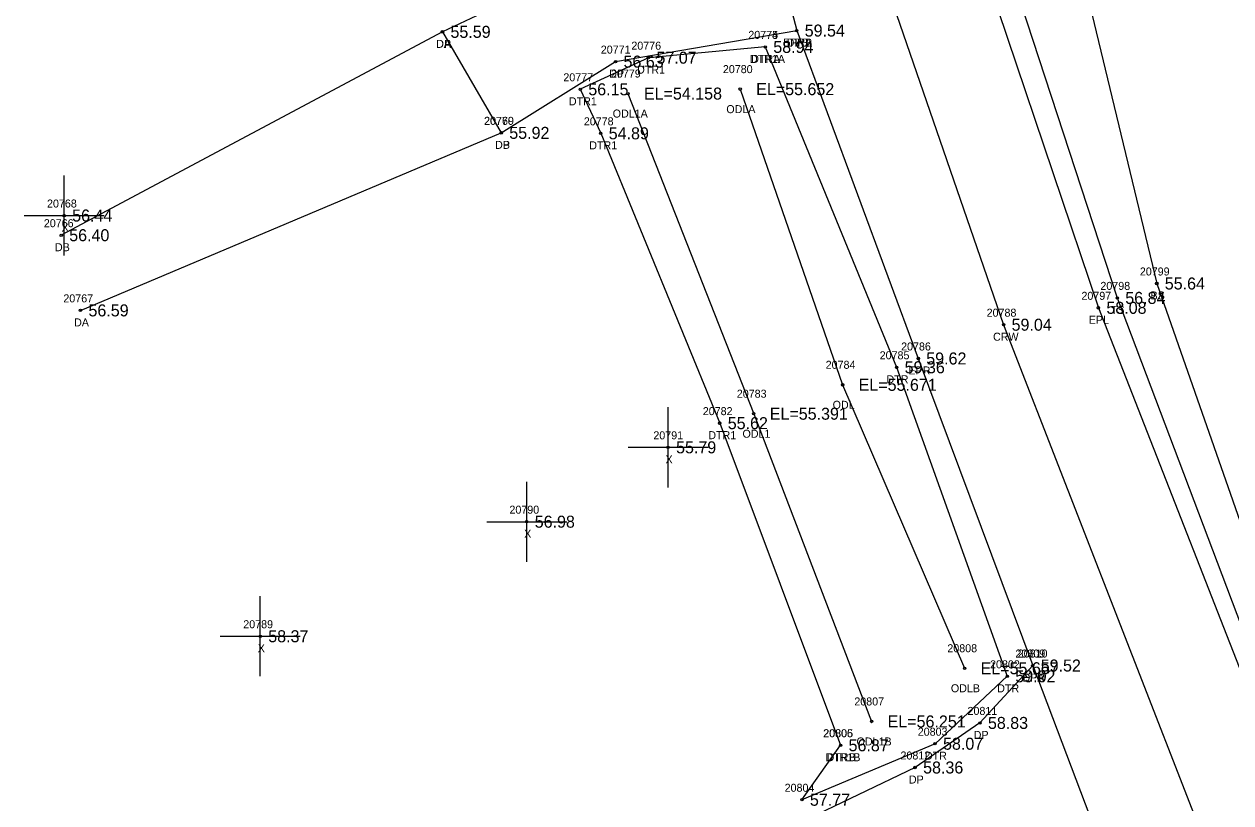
# Model space of a CAD drawing. Extents: x 2396547 to 2397655, y 770185 to 772649.
# Drawn here: x 2396996.6 to 2397147.4, y 771116.1 to 771213.4 of the extents above; entities that cross this region are included whole.
import ezdxf

# ---------------------------------------------------------------- set-up
doc = ezdxf.new("R2010")
doc.units = 0
for name, color, linetype in [('RD_DTM_BkLn1', 7, 'Continuous'), ('RD_DTM_BkLn2', 7, 'Continuous'), ('RD_DTM_BkLn_txCode', 7, 'Continuous'), ('RD_EX_Driveway', 7, 'Continuous'), ('RD_EX_Driveway_txCode', 7, 'Continuous'), ('RD_EX_H2O', 7, 'Continuous'), ('RD_EX_H2O_txCode', 7, 'Continuous'), ('RD_EX_Misc', 7, 'Continuous'), ('RD_EX_Misc_txCode', 7, 'Continuous'), ('RD_EX_Road', 7, 'Continuous'), ('RD_EX_Road_txCode', 7, 'Continuous'), ('RD_EX_TX_Driveway_ELEV', 7, 'Continuous'), ('RD_EX_TX_H2O_ELEV', 7, 'Continuous'), ('RD_EX_TX_Misc_ELEV', 7, 'Continuous'), ('RD_EX_TX_Road_ELEV', 7, 'Continuous'), ('RD_HC_Survey_ELEV', 7, 'Continuous'), ('RD_HC_Survey_txCode', 7, 'Continuous'), ('RD_SMD_Locator', 7, 'Continuous')]:
    doc.layers.add(name, color=color, linetype=linetype)

msp = doc.modelspace()

# ---------------------------------------------------------------- linework, layer by layer
at = {"layer": 'RD_DTM_BkLn1'}
msp.add_lwpolyline([(2397104.78, 771217.07), (2397119.02, 771175.87), (2397143.13, 771113.88), (2397170.45, 771052.64), (2397197.01, 770999.9), (2397235.12, 770930.63), (2397270.14, 770871.5)], dxfattribs=at)
at = {"layer": 'RD_DTM_BkLn2'}
for points in [[(2397076.78, 771367.04), (2397097.18, 771355.59), (2397095.19, 771340.51), (2397107.46, 771294.95), (2397125.86, 771232.19), (2397125.86, 771232.19), (2397138.17, 771181.02), (2397159.24, 771120.76), (2397175.38, 771088.12), (2397179.45, 771097.49), (2397196.45, 771092.84), (2397253.33, 771096.54)], [(2397076.87, 771363.73), (2397092.63, 771353.52), (2397090.96, 771344.27), (2397084.99, 771338.48), (2397096.6, 771290.87), (2397116.69, 771229.78), (2397116.69, 771229.78), (2397133.23, 771179.22), (2397155.87, 771119.34), (2397173.3, 771081.82), (2397181.13, 771084.07), (2397253.33, 771087)]]:
    msp.add_lwpolyline(points, dxfattribs=at)
at = {"layer": 'RD_EX_Driveway'}
for p, q in [((2397048.88, 771212.46), (2397001.22, 771187.05)), ((2397003.63, 771177.66), (2397056.23, 771199.84))]:
    msp.add_line(p, q, dxfattribs=at)
for points in [[(2397086.26, 771238.89), (2397083.76, 771232.99), (2397079.93, 771229.79), (2397073.08, 771224.62), (2397063.07, 771219.15), (2397048.88, 771212.46), (2397056.23, 771199.84), (2397070.51, 771208.74), (2397093.16, 771212.62)], [(2397122.66, 771133.29), (2397116.06, 771126.12), (2397107.96, 771120.55), (2397093.7, 771113.7), (2397099.75, 771102.64), (2397113.7, 771107.54), (2397125.39, 771110.49), (2397131.66, 771109.5)]]:
    msp.add_lwpolyline(points, dxfattribs=at)
at = {"layer": 'RD_EX_H2O'}
for points in [[(2397089.23, 771210.58), (2397074.63, 771209.23), (2397066.11, 771205.28), (2397068.66, 771199.78), (2397083.54, 771163.57), (2397098.64, 771123.33)], [(2397089.23, 771210.58), (2397105.65, 771170.55), (2397119.48, 771131.94), (2397110.45, 771123.52), (2397093.81, 771116.52), (2397098.64, 771123.33)], [(2397072.06, 771204.75), (2397087.79, 771164.75), (2397102.52, 771126.3)], [(2397086.09, 771205.3), (2397098.9, 771168.36), (2397114.14, 771132.95)]]:
    msp.add_lwpolyline(points, dxfattribs=at)
at = {"layer": 'RD_EX_Misc'}
for p, q in [((2397001.59, 771184.51), (2397001.59, 771194.51)), ((2396996.59, 771189.51), (2397006.59, 771189.51)), ((2397077.08, 771155.55), (2397077.08, 771165.55)), ((2397072.08, 771160.55), (2397082.08, 771160.55)), ((2397059.41, 771146.26), (2397059.41, 771156.26)), ((2397054.41, 771151.26), (2397064.41, 771151.26)), ((2397026.1, 771131.95), (2397026.1, 771141.95)), ((2397021.1, 771136.95), (2397031.1, 771136.95))]:
    msp.add_line(p, q, dxfattribs=at)
at = {"layer": 'RD_EX_Road'}
for points in [[(2397051, 771358.07), (2397072.97, 771279.15), (2397086.26, 771238.89), (2397093.16, 771212.62)], [(2397113.76, 771228.75), (2397130.87, 771177.98), (2397154.19, 771118.49), (2397170.38, 771081.25), (2397178.53, 771063.49), (2397207.96, 771004.56), (2397238.54, 770949.11), (2397245.72, 770936.59), (2397280.76, 770876.73)], [(2397093.16, 771212.62), (2397108.35, 771171.65), (2397122.66, 771133.29), (2397131.66, 771109.5), (2397159.86, 771046.96), (2397187.02, 770992.86), (2397227.29, 770920.43), (2397260.16, 770864.73)]]:
    msp.add_lwpolyline(points, dxfattribs=at)
at = {"layer": 'RD_SMD_Locator'}
for centre in [(2397048.88, 771212.46), (2397048.88, 771212.46), (2397093.16, 771212.62), (2397093.16, 771212.62), (2397093.16, 771212.62), (2397089.23, 771210.58), (2397089.23, 771210.58), (2397074.63, 771209.23), (2397070.51, 771208.74), (2397066.11, 771205.28), (2397072.06, 771204.75), (2397086.09, 771205.3), (2397056.23, 771199.84), (2397056.23, 771199.84), (2397068.66, 771199.78), (2397001.59, 771189.51), (2397001.22, 771187.05), (2397138.17, 771181.02), (2397133.23, 771179.22), (2397003.63, 771177.66), (2397130.87, 771177.98), (2397119.02, 771175.87), (2397108.35, 771171.65), (2397105.65, 771170.55), (2397098.9, 771168.36), (2397087.79, 771164.75), (2397083.54, 771163.57), (2397077.08, 771160.55), (2397059.41, 771151.26), (2397026.1, 771136.95), (2397114.14, 771132.95), (2397122.66, 771133.29), (2397122.66, 771133.29), (2397119.48, 771131.94), (2397102.52, 771126.3), (2397116.06, 771126.12), (2397098.64, 771123.33), (2397098.64, 771123.33), (2397110.45, 771123.52), (2397107.96, 771120.55), (2397093.81, 771116.52)]:
    msp.add_circle(centre, 0.15, dxfattribs=at)

# ---------------------------------------------------------------- texts
at = {"layer": 'RD_DTM_BkLn_txCode'}
for s, p in [('20799', (2397136.05, 771182.02)), ('20798', (2397131.12, 771180.22)), ('BS', (2397137.39, 771179.02)), ('TS', (2397132.44, 771177.22))]:
    msp.add_text(s, height=1, dxfattribs=at).set_placement(p)
at = {"layer": 'RD_EX_Driveway_txCode'}
for s, p in [('DA', (2397048.08, 771210.46)), ('DP', (2397048.1, 771210.46)), ('20771', (2397068.67, 771209.74)), ('DPB', (2397091.9, 771210.62)), ('DP', (2397069.73, 771206.74)), ('20770', (2397054.07, 771200.84)), ('20769', (2397054.09, 771200.84)), ('DB', (2397055.45, 771197.84)), ('DP', (2397055.45, 771197.84)), ('20766', (2396999.05, 771188.05)), ('DB', (2397000.44, 771185.05)), ('20767', (2397001.49, 771178.66)), ('DA', (2397002.83, 771175.66)), ('20810', (2397120.79, 771134.29)), ('DPA', (2397121.39, 771131.29)), ('20811', (2397114.51, 771127.12)), ('DP', (2397115.28, 771124.12)), ('20812', (2397106.13, 771121.55)), ('DP', (2397107.18, 771118.55))]:
    msp.add_text(s, height=1, dxfattribs=at).set_placement(p)
at = {"layer": 'RD_EX_H2O_txCode'}
for s, p in [('20774', (2397087.11, 771211.58)), ('20775', (2397087.11, 771211.58)), ('20776', (2397072.49, 771210.23)), ('DTR1A', (2397087.31, 771208.58)), ('DTRA', (2397087.47, 771208.58)), ('20779', (2397069.94, 771206.75)), ('DTR1', (2397073.2, 771207.23)), ('20780', (2397083.93, 771207.3)), ('20777', (2397063.99, 771206.28)), ('DTR1', (2397064.68, 771203.28)), ('ODLA', (2397084.36, 771202.3)), ('20778', (2397066.55, 771200.78)), ('ODL1A', (2397070.16, 771201.75)), ('DTR1', (2397067.23, 771197.78)), ('20785', (2397103.53, 771171.55)), ('20784', (2397096.78, 771170.36)), ('DTR', (2397104.38, 771168.55)), ('20783', (2397085.67, 771166.75)), ('20782', (2397081.42, 771164.57)), ('ODL', (2397097.65, 771165.36)), ('DTR1', (2397082.11, 771161.57)), ('ODL1', (2397086.38, 771161.75)), ('20808', (2397111.99, 771134.95)), ('20802', (2397117.33, 771132.94)), ('ODLB', (2397112.43, 771129.95)), ('DTR', (2397118.22, 771129.94)), ('20807', (2397100.36, 771128.3)), ('20806', (2397096.46, 771124.33)), ('20805', (2397096.49, 771124.33)), ('20803', (2397108.29, 771124.52)), ('ODL1B', (2397100.64, 771123.3)), ('DTR1B', (2397096.74, 771121.33)), ('DTRB', (2397096.9, 771121.33)), ('DTR', (2397109.18, 771121.52)), ('20804', (2397091.65, 771117.52))]:
    msp.add_text(s, height=1, dxfattribs=at).set_placement(p)
at = {"layer": 'RD_EX_Misc_txCode'}
for s, p in [('20768', (2396999.45, 771190.51)), ('X', (2397001.27, 771187.51)), ('20791', (2397075.24, 771161.55)), ('X', (2397076.76, 771158.55)), ('20790', (2397057.25, 771152.26)), ('X', (2397059.09, 771149.26)), ('20789', (2397023.98, 771137.95)), ('X', (2397025.79, 771134.95))]:
    msp.add_text(s, height=1, dxfattribs=at).set_placement(p)
at = {"layer": 'RD_EX_Road_txCode'}
for s, p in [('EPRA', (2397091.44, 771210.62)), ('EPRB', (2397091.46, 771210.62)), ('20797', (2397128.75, 771178.98)), ('EPL', (2397129.67, 771175.98)), ('20786', (2397106.21, 771172.65)), ('EPR', (2397107.12, 771169.65)), ('20809', (2397120.5, 771134.29)), ('EPR', (2397121.43, 771131.29))]:
    msp.add_text(s, height=1, dxfattribs=at).set_placement(p)
at = {"layer": 'RD_EX_TX_Driveway_ELEV'}
for s, p in [('55.59', (2397049.88, 771211.71)), ('55.59', (2397049.88, 771211.71)), ('59.54', (2397094.16, 771211.87)), ('56.63', (2397071.51, 771207.99)), ('55.92', (2397057.23, 771199.09)), ('55.92', (2397057.23, 771199.09)), ('56.40', (2397002.22, 771186.3)), ('56.59', (2397004.63, 771176.91)), ('59.52', (2397123.66, 771132.54)), ('58.83', (2397117.06, 771125.37)), ('58.36', (2397108.96, 771119.8))]:
    msp.add_text(s, height=1.5, dxfattribs=at).set_placement(p)
at = {"layer": 'RD_EX_TX_H2O_ELEV'}
for s, p in [('58.94', (2397090.23, 771209.83)), ('58.94', (2397090.23, 771209.83)), ('57.07', (2397075.63, 771208.48)), ('56.15', (2397067.11, 771204.53)), ('EL=54.158', (2397074.06, 771204)), ('EL=55.652', (2397088.09, 771204.55)), ('54.89', (2397069.66, 771199.03)), ('59.36', (2397106.65, 771169.8)), ('EL=55.671', (2397100.9, 771167.61)), ('EL=55.391', (2397089.79, 771164)), ('55.62', (2397084.54, 771162.82)), ('EL=55.657', (2397116.14, 771132.2)), ('59.02', (2397120.48, 771131.19)), ('EL=56.251', (2397104.52, 771125.55)), ('56.87', (2397099.64, 771122.58)), ('56.87', (2397099.64, 771122.58)), ('58.07', (2397111.45, 771122.77)), ('57.77', (2397094.81, 771115.77))]:
    msp.add_text(s, height=1.5, dxfattribs=at).set_placement(p)
at = {"layer": 'RD_EX_TX_Misc_ELEV'}
for s, p in [('56.44', (2397002.59, 771188.76)), ('55.64', (2397139.17, 771180.27)), ('56.84', (2397134.23, 771178.47)), ('55.79', (2397078.08, 771159.8)), ('56.98', (2397060.41, 771150.51)), ('58.37', (2397027.1, 771136.2))]:
    msp.add_text(s, height=1.5, dxfattribs=at).set_placement(p)
at = {"layer": 'RD_EX_TX_Road_ELEV'}
for s, p in [('59.54', (2397094.16, 771211.87)), ('59.54', (2397094.16, 771211.87)), ('58.08', (2397131.87, 771177.23)), ('59.62', (2397109.35, 771170.9)), ('59.52', (2397123.66, 771132.54))]:
    msp.add_text(s, height=1.5, dxfattribs=at).set_placement(p)
at = {"layer": 'RD_HC_Survey_ELEV'}
msp.add_text('59.04', height=1.5, dxfattribs=at).set_placement((2397120.02, 771175.12))
at = {"layer": 'RD_HC_Survey_txCode'}
for s, p in [('20788', (2397116.9, 771176.87)), ('CRW', (2397117.7, 771173.87))]:
    msp.add_text(s, height=1, dxfattribs=at).set_placement(p)

doc.saveas('drawing.dxf')
